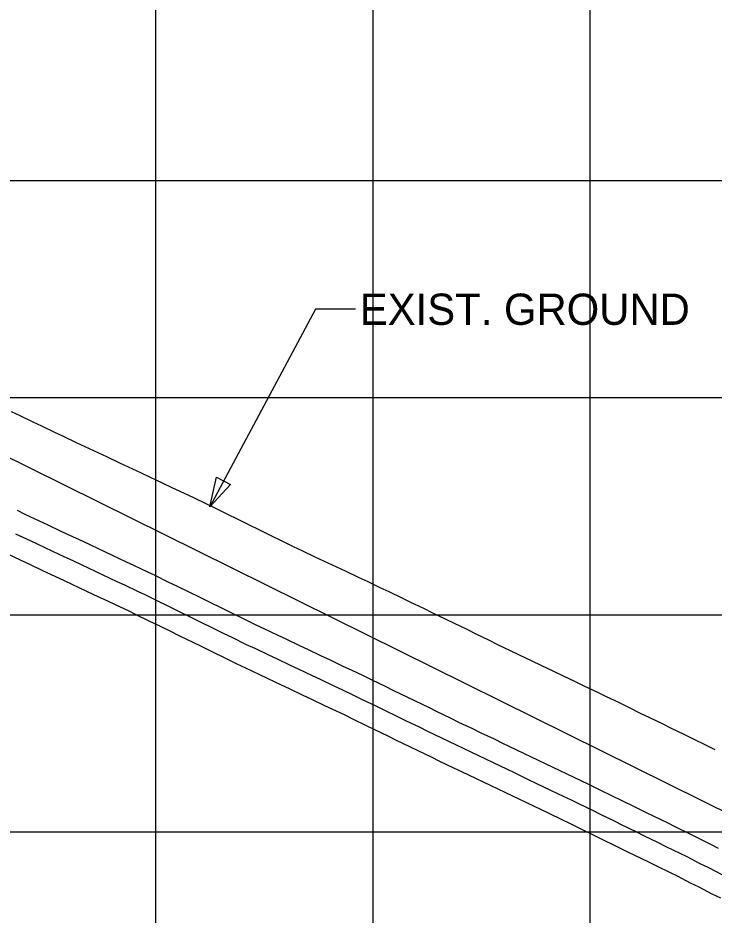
# Model space of a CAD drawing. Extents: x -7164 to 2214450, y -19642 to 253469.
# Drawn here: x 2918.3 to 3078.5, y -1919.1 to -1712.6 of the extents above; entities that cross this region are included whole.
import ezdxf

# ---------------------------------------------------------------- set-up
doc = ezdxf.new("R2010")
doc.units = 0
for name, color, linetype in [('DESIGN - PROFILE - Proposed', 7, 'Continuous'), ('DESIGN - PROFILE - Proposed Text', 7, 'Continuous'), ('DESIGN - SHEET - Light Grid', 7, 'Continuous'), ('SURVEY - PROFILE - Ground Line with Text', 7, 'Continuous'), ('SURVEY - PROFILE - Utilities - Cable with Text', 7, 'Continuous'), ('SURVEY - PROFILE - Utilities - Electric with Text', 7, 'Continuous'), ('XTREE', 7, 'Continuous')]:
    doc.layers.add(name, color=color, linetype=linetype)

msp = doc.modelspace()

# ---------------------------------------------------------------- linework, layer by layer
at = {"layer": 'DESIGN - PROFILE - Proposed'}
msp.add_line((2660.96, -1687.48), (3497.5, -2101.57), dxfattribs=at)
msp.add_line((2660.96, -1687.48), (3497.5, -2101.57), dxfattribs=at)
at = {"layer": 'DESIGN - PROFILE - Proposed Text'}
msp.add_lwpolyline([(2995.96, -1779.67), (2986.78, -1779.67), (2962.41, -1825.13)], dxfattribs=at)
msp.add_lwpolyline([(2995.96, -1779.67), (2986.78, -1779.67), (2962.41, -1825.13)], dxfattribs=at)
msp.add_lwpolyline([(2967.2, -1820.03), (2962.41, -1825.13), (2964, -1818.32)], close=True, dxfattribs=at)
msp.add_lwpolyline([(2967.2, -1820.03), (2962.41, -1825.13), (2964, -1818.32)], close=True, dxfattribs=at)
at = {"layer": 'DESIGN - SHEET - Light Grid'}
for p, q in [((2950, -3000), (2950, -1000)), ((2950, -3000), (2950, -1000)), ((3000, -3000), (3000, -1000)), ((3000, -3000), (3000, -1000)), ((3050, -3000), (3050, -1000)), ((3050, -3000), (3050, -1000)), ((0, -1750), (12400, -1750)), ((0, -1750), (12400, -1750)), ((0, -1800), (12400, -1800)), ((0, -1800), (12400, -1800)), ((0, -1850), (12400, -1850)), ((0, -1850), (12400, -1850)), ((0, -1900), (12400, -1900)), ((0, -1900), (12400, -1900))]:
    msp.add_line(p, q, dxfattribs=at)
at = {"layer": 'SURVEY - PROFILE - Ground Line with Text'}
for points in [[(2916.69, -1803.18), (2918.67, -1804.14), (2921.68, -1805.56), (2923.66, -1806.52), (2926.68, -1807.94), (2928.65, -1808.9), (2931.67, -1810.33), (2933.64, -1811.25), (2936.67, -1812.67), (2938.62, -1813.59), (2941.66, -1815.02), (2943.6, -1815.93)], [(2916.69, -1803.18), (2918.67, -1804.14), (2921.68, -1805.56), (2923.66, -1806.52), (2926.68, -1807.94), (2928.65, -1808.9), (2931.67, -1810.33), (2933.64, -1811.25), (2936.67, -1812.67), (2938.62, -1813.59), (2941.66, -1815.02), (2943.6, -1815.93)], [(2943.6, -1815.93), (2946.65, -1817.37), (2948.58, -1818.27), (2951.65, -1819.71), (2953.56, -1820.61), (2956.64, -1822.06), (2958.55, -1822.97), (2961.64, -1824.51), (2963.56, -1825.42), (2966.63, -1826.95), (2968.57, -1827.87), (2971.63, -1829.39), (2973.58, -1830.32), (2976.62, -1831.84), (2978.58, -1832.77), (2981.61, -1834.28), (2983.59, -1835.19), (2986.61, -1836.64), (2988.6, -1837.56), (2991.6, -1839), (2993.62, -1839.93), (2996.6, -1841.36), (2998.63, -1842.3), (3001.59, -1843.72), (3003.64, -1844.67), (3006.59, -1846.08), (3008.66, -1847.12), (3011.58, -1848.51), (3013.65, -1849.55), (3016.57, -1850.93), (3018.65, -1851.98), (3021.57, -1853.36), (3023.65, -1854.41), (3026.56, -1855.79), (3028.65, -1856.84), (3031.56, -1858.22), (3033.65, -1859.24), (3036.55, -1860.61), (3038.65, -1861.64), (3041.54, -1863), (3043.64, -1864.03), (3046.54, -1865.39), (3048.64, -1866.42), (3051.53, -1867.78), (3053.63, -1868.81), (3056.53, -1870.17), (3058.63, -1871.22), (3061.52, -1872.63), (3063.64, -1873.68), (3066.52, -1875.08), (3068.65, -1876.14), (3071.51, -1877.53), (3073.66, -1878.6), (3076.5, -1879.98), (3078.67, -1881.06)], [(2943.6, -1815.93), (2946.65, -1817.37), (2948.58, -1818.27), (2951.65, -1819.71), (2953.56, -1820.61), (2956.64, -1822.06), (2958.55, -1822.97), (2961.64, -1824.51), (2963.56, -1825.42), (2966.63, -1826.95), (2968.57, -1827.87), (2971.63, -1829.39), (2973.58, -1830.32), (2976.62, -1831.84), (2978.58, -1832.77), (2981.61, -1834.28), (2983.59, -1835.19), (2986.61, -1836.64), (2988.6, -1837.56), (2991.6, -1839), (2993.62, -1839.93), (2996.6, -1841.36), (2998.63, -1842.3), (3001.59, -1843.72), (3003.64, -1844.67), (3006.59, -1846.08), (3008.66, -1847.12), (3011.58, -1848.51), (3013.65, -1849.55), (3016.57, -1850.93), (3018.65, -1851.98), (3021.57, -1853.36), (3023.65, -1854.41), (3026.56, -1855.79), (3028.65, -1856.84), (3031.56, -1858.22), (3033.65, -1859.24), (3036.55, -1860.61), (3038.65, -1861.64), (3041.54, -1863), (3043.64, -1864.03), (3046.54, -1865.39), (3048.64, -1866.42), (3051.53, -1867.78), (3053.63, -1868.81), (3056.53, -1870.17), (3058.63, -1871.22), (3061.52, -1872.63), (3063.64, -1873.68), (3066.52, -1875.08), (3068.65, -1876.14), (3071.51, -1877.53), (3073.66, -1878.6), (3076.5, -1879.98), (3078.67, -1881.06)]]:
    msp.add_lwpolyline(points, dxfattribs=at)
at = {"layer": 'SURVEY - PROFILE - Utilities - Cable with Text'}
msp.add_lwpolyline([(2915.55, -1835.86), (2918.92, -1837.45), (2920.74, -1838.3), (2923.92, -1839.8), (2925.72, -1840.64), (2928.92, -1842.15), (2930.7, -1842.98), (2933.91, -1844.5), (2935.68, -1845.32), (2938.9, -1846.84), (2940.65, -1847.66), (2943.8, -1849.14), (2945.25, -1849.84), (2948.51, -1851.46), (2950.26, -1852.29), (2953.5, -1853.9), (2955.27, -1854.75), (2958.5, -1856.35), (2960.28, -1857.2), (2963.49, -1858.8), (2965.29, -1859.65), (2968.67, -1861.33), (2970.64, -1862.24), (2973.84, -1863.78), (2975.66, -1864.62), (2978.83, -1866.14), (2980.67, -1866.99), (2983.83, -1868.51), (2985.69, -1869.36), (2988.82, -1870.87), (2990.7, -1871.74), (2993.33, -1873), (2995.31, -1874), (2998.42, -1875.47), (3000.31, -1876.42), (3003.41, -1877.89), (3005.31, -1878.85), (3008.4, -1880.31), (3010.3, -1881.27), (3013.4, -1882.73), (3015.3, -1883.69), (3018.55, -1885.23), (3020.48, -1886.17), (3023.57, -1887.63), (3025.47, -1888.56), (3028.56, -1890.01), (3030.47, -1890.95), (3033.55, -1892.4), (3035.46, -1893.34), (3038.55, -1894.79), (3040.45, -1895.72), (3043.45, -1897.13), (3045.2, -1898.01), (3048.29, -1899.5), (3050.21, -1900.46), (3053.28, -1901.95), (3055.21, -1902.91), (3058.28, -1904.4), (3060.22, -1905.37), (3063.27, -1906.85), (3065.22, -1907.82), (3068.43, -1909.37), (3069.98, -1910.13), (3073.01, -1911.71), (3074.97, -1912.66), (3078.01, -1914.24), (3079.95, -1915.19)], dxfattribs=at)
msp.add_lwpolyline([(2915.55, -1835.86), (2918.92, -1837.45), (2920.74, -1838.3), (2923.92, -1839.8), (2925.72, -1840.64), (2928.92, -1842.15), (2930.7, -1842.98), (2933.91, -1844.5), (2935.68, -1845.32), (2938.9, -1846.84), (2940.65, -1847.66), (2943.8, -1849.14), (2945.25, -1849.84), (2948.51, -1851.46), (2950.26, -1852.29), (2953.5, -1853.9), (2955.27, -1854.75), (2958.5, -1856.35), (2960.28, -1857.2), (2963.49, -1858.8), (2965.29, -1859.65), (2968.67, -1861.33), (2970.64, -1862.24), (2973.84, -1863.78), (2975.66, -1864.62), (2978.83, -1866.14), (2980.67, -1866.99), (2983.83, -1868.51), (2985.69, -1869.36), (2988.82, -1870.87), (2990.7, -1871.74), (2993.33, -1873), (2995.31, -1874), (2998.42, -1875.47), (3000.31, -1876.42), (3003.41, -1877.89), (3005.31, -1878.85), (3008.4, -1880.31), (3010.3, -1881.27), (3013.4, -1882.73), (3015.3, -1883.69), (3018.55, -1885.23), (3020.48, -1886.17), (3023.57, -1887.63), (3025.47, -1888.56), (3028.56, -1890.01), (3030.47, -1890.95), (3033.55, -1892.4), (3035.46, -1893.34), (3038.55, -1894.79), (3040.45, -1895.72), (3043.45, -1897.13), (3045.2, -1898.01), (3048.29, -1899.5), (3050.21, -1900.46), (3053.28, -1901.95), (3055.21, -1902.91), (3058.28, -1904.4), (3060.22, -1905.37), (3063.27, -1906.85), (3065.22, -1907.82), (3068.43, -1909.37), (3069.98, -1910.13), (3073.01, -1911.71), (3074.97, -1912.66), (3078.01, -1914.24), (3079.95, -1915.19)], dxfattribs=at)
at = {"layer": 'SURVEY - PROFILE - Utilities - Electric with Text'}
for points in [[(2918.05, -1825.96), (2919.87, -1826.84), (2923.17, -1828.4), (2924.99, -1829.25), (2928.17, -1830.75), (2929.97, -1831.59), (2933.17, -1833.1), (2934.95, -1833.93), (2938.16, -1835.44), (2939.92, -1836.27), (2943.15, -1837.79), (2944.9, -1838.61), (2948.08, -1840.11), (2949.63, -1840.85), (2952.89, -1842.47), (2954.64, -1843.3), (2957.88, -1844.91), (2959.65, -1845.75), (2962.88, -1847.36), (2964.65, -1848.21), (2967.87, -1849.81), (2969.66, -1850.66), (2972.99, -1852.31), (2974.9, -1853.19), (2978.1, -1854.73), (2979.92, -1855.57), (2983.09, -1857.1), (2984.93, -1857.94), (2988.09, -1859.46), (2989.94, -1860.31), (2993.08, -1861.82), (2994.96, -1862.69), (2997.75, -1864.03), (2999.7, -1865.01), (3002.8, -1866.48), (3004.7, -1867.44), (3007.8, -1868.9), (3009.7, -1869.86), (3012.79, -1871.32), (3014.69, -1872.28), (3017.79, -1873.75), (3019.69, -1874.71), (3022.88, -1876.22), (3024.81, -1877.16), (3027.89, -1878.61), (3029.8, -1879.55), (3032.89, -1881), (3034.8, -1881.93), (3037.88, -1883.39), (3039.79, -1884.32), (3042.88, -1885.78), (3044.78, -1886.71), (3047.81, -1888.13), (3049.61, -1889.03), (3052.7, -1890.53), (3054.62, -1891.49), (3057.7, -1892.98), (3059.62, -1893.94), (3062.69, -1895.43), (3064.63, -1896.39), (3067.68, -1897.87), (3069.64, -1898.85), (3072.79, -1900.37), (3074.47, -1901.19), (3077.51, -1902.78), (3079.46, -1903.72)], [(2918.05, -1825.96), (2919.87, -1826.84), (2923.17, -1828.4), (2924.99, -1829.25), (2928.17, -1830.75), (2929.97, -1831.59), (2933.17, -1833.1), (2934.95, -1833.93), (2938.16, -1835.44), (2939.92, -1836.27), (2943.15, -1837.79), (2944.9, -1838.61), (2948.08, -1840.11), (2949.63, -1840.85), (2952.89, -1842.47), (2954.64, -1843.3), (2957.88, -1844.91), (2959.65, -1845.75), (2962.88, -1847.36), (2964.65, -1848.21), (2967.87, -1849.81), (2969.66, -1850.66), (2972.99, -1852.31), (2974.9, -1853.19), (2978.1, -1854.73), (2979.92, -1855.57), (2983.09, -1857.1), (2984.93, -1857.94), (2988.09, -1859.46), (2989.94, -1860.31), (2993.08, -1861.82), (2994.96, -1862.69), (2997.75, -1864.03), (2999.7, -1865.01), (3002.8, -1866.48), (3004.7, -1867.44), (3007.8, -1868.9), (3009.7, -1869.86), (3012.79, -1871.32), (3014.69, -1872.28), (3017.79, -1873.75), (3019.69, -1874.71), (3022.88, -1876.22), (3024.81, -1877.16), (3027.89, -1878.61), (3029.8, -1879.55), (3032.89, -1881), (3034.8, -1881.93), (3037.88, -1883.39), (3039.79, -1884.32), (3042.88, -1885.78), (3044.78, -1886.71), (3047.81, -1888.13), (3049.61, -1889.03), (3052.7, -1890.53), (3054.62, -1891.49), (3057.7, -1892.98), (3059.62, -1893.94), (3062.69, -1895.43), (3064.63, -1896.39), (3067.68, -1897.87), (3069.64, -1898.85), (3072.79, -1900.37), (3074.47, -1901.19), (3077.51, -1902.78), (3079.46, -1903.72)], [(2917.71, -1831.35), (2921.05, -1832.93), (2922.87, -1833.78), (2926.05, -1835.28), (2927.84, -1836.12), (2931.04, -1837.62), (2932.82, -1838.46), (2936.04, -1839.97), (2937.8, -1840.8), (2941.03, -1842.32), (2942.78, -1843.14), (2945.94, -1844.63), (2947.44, -1845.34), (2950.7, -1846.96), (2952.45, -1847.8), (2955.69, -1849.41), (2957.46, -1850.25), (2960.69, -1851.86), (2962.47, -1852.7), (2965.68, -1854.3), (2967.47, -1855.16), (2970.83, -1856.82), (2972.77, -1857.72), (2975.97, -1859.25), (2977.79, -1860.09), (2980.96, -1861.62), (2982.8, -1862.47), (2985.96, -1863.99), (2987.81, -1864.84), (2990.95, -1866.35), (2992.83, -1867.21), (2995.54, -1868.52), (2997.51, -1869.51), (3000.61, -1870.98), (3002.5, -1871.93), (3005.6, -1873.4), (3007.5, -1874.35), (3010.6, -1875.82), (3012.5, -1876.78), (3015.59, -1878.24), (3017.5, -1879.2), (3020.72, -1880.72), (3022.65, -1881.67), (3025.73, -1883.12), (3027.64, -1884.05), (3030.72, -1885.51), (3032.63, -1886.44), (3035.72, -1887.9), (3037.62, -1888.83), (3040.71, -1890.28), (3042.62, -1891.22), (3045.63, -1892.63), (3047.41, -1893.52), (3050.5, -1895.02), (3052.41, -1895.97), (3055.49, -1897.46), (3057.42, -1898.43), (3060.48, -1899.91), (3062.42, -1900.88), (3065.48, -1902.36), (3067.43, -1903.34), (3070.61, -1904.87), (3072.23, -1905.66), (3075.26, -1907.24), (3077.21, -1908.19), (3080.25, -1909.78)], [(2917.71, -1831.35), (2921.05, -1832.93), (2922.87, -1833.78), (2926.05, -1835.28), (2927.84, -1836.12), (2931.04, -1837.62), (2932.82, -1838.46), (2936.04, -1839.97), (2937.8, -1840.8), (2941.03, -1842.32), (2942.78, -1843.14), (2945.94, -1844.63), (2947.44, -1845.34), (2950.7, -1846.96), (2952.45, -1847.8), (2955.69, -1849.41), (2957.46, -1850.25), (2960.69, -1851.86), (2962.47, -1852.7), (2965.68, -1854.3), (2967.47, -1855.16), (2970.83, -1856.82), (2972.77, -1857.72), (2975.97, -1859.25), (2977.79, -1860.09), (2980.96, -1861.62), (2982.8, -1862.47), (2985.96, -1863.99), (2987.81, -1864.84), (2990.95, -1866.35), (2992.83, -1867.21), (2995.54, -1868.52), (2997.51, -1869.51), (3000.61, -1870.98), (3002.5, -1871.93), (3005.6, -1873.4), (3007.5, -1874.35), (3010.6, -1875.82), (3012.5, -1876.78), (3015.59, -1878.24), (3017.5, -1879.2), (3020.72, -1880.72), (3022.65, -1881.67), (3025.73, -1883.12), (3027.64, -1884.05), (3030.72, -1885.51), (3032.63, -1886.44), (3035.72, -1887.9), (3037.62, -1888.83), (3040.71, -1890.28), (3042.62, -1891.22), (3045.63, -1892.63), (3047.41, -1893.52), (3050.5, -1895.02), (3052.41, -1895.97), (3055.49, -1897.46), (3057.42, -1898.43), (3060.48, -1899.91), (3062.42, -1900.88), (3065.48, -1902.36), (3067.43, -1903.34), (3070.61, -1904.87), (3072.23, -1905.66), (3075.26, -1907.24), (3077.21, -1908.19), (3080.25, -1909.78)]]:
    msp.add_lwpolyline(points, dxfattribs=at)
at = {"layer": 'XTREE'}
msp.add_line((2273.46, -1495.67), (3810, -2256.26), dxfattribs=at)
msp.add_line((2273.46, -1495.67), (3810, -2256.26), dxfattribs=at)

# ---------------------------------------------------------------- texts
at = {"layer": 'DESIGN - PROFILE - Proposed Text'}
msp.add_text('EXIST. GROUND', height=7.2, dxfattribs=at).set_placement((2996.96, -1783.27))
msp.add_text('EXIST. GROUND', height=7.2, dxfattribs=at).set_placement((2996.96, -1783.27))

doc.saveas('drawing.dxf')
